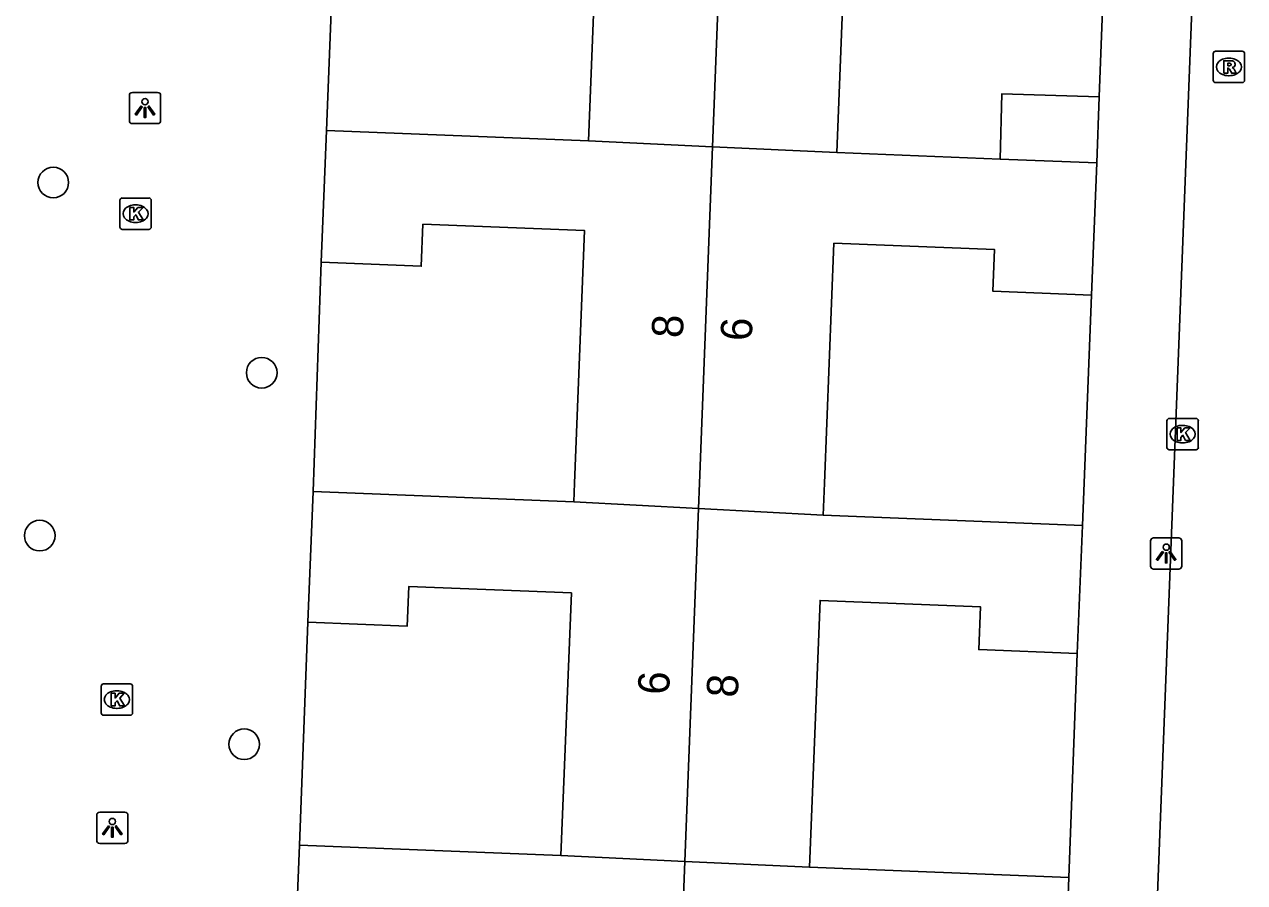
# Model space of a CAD drawing. Extents: x 160787 to 161428, y 386828 to 387483.
# Drawn here: x 161235.24 to 161274.2, y 387237.25 to 387264.64 of the extents above; entities that cross this region are included whole.
import ezdxf

# ---------------------------------------------------------------- set-up
doc = ezdxf.new("R2010")
doc.units = 0
for name, color, linetype in [('IMGEO_Boom', 7, 'Continuous'), ('IMGEO_Kolk', 7, 'Continuous'), ('IMGEO_Lichtpunt', 7, 'Continuous'), ('IMGEO_Muur', 7, 'Continuous'), ('IMGEO_Pand', 7, 'Continuous'), ('IMGEO_Pand_nummerreeks', 7, 'Continuous'), ('IMGEO_Rioolput', 7, 'Continuous'), ('IMGEO_Voetpad_open', 7, 'Continuous')]:
    doc.layers.add(name, color=color, linetype=linetype)

msp = doc.modelspace()

# ---------------------------------------------------------------- linework, layer by layer
at = {"layer": 'IMGEO_Boom'}
for centre in [(161236.166, 387259.594), (161242.821, 387253.522), (161235.734, 387248.322), (161242.262, 387241.662)]:
    msp.add_circle(centre, 0.489, dxfattribs=at)
at = {"layer": 'IMGEO_Kolk'}
for p, q in [((161238.294, 387258.174), (161238.294, 387259.026)), ((161238.369, 387259.1), (161239.221, 387259.1)), ((161238.782, 387258.88), (161238.807, 387258.88)), ((161239.295, 387259.026), (161239.295, 387258.174)), ((161239.221, 387258.1), (161238.369, 387258.1)), ((161238.805, 387258.32), (161238.78, 387258.32)), ((161271.725, 387251.137), (161271.725, 387251.989)), ((161271.8, 387252.063), (161272.652, 387252.063)), ((161272.213, 387251.843), (161272.238, 387251.843)), ((161272.726, 387251.989), (161272.726, 387251.137)), ((161272.652, 387251.063), (161271.8, 387251.063)), ((161272.236, 387251.283), (161272.211, 387251.283)), ((161237.696, 387242.663), (161237.696, 387243.515)), ((161237.771, 387243.589), (161238.623, 387243.589)), ((161238.184, 387243.369), (161238.209, 387243.369)), ((161238.697, 387243.515), (161238.697, 387242.663)), ((161238.623, 387242.589), (161237.771, 387242.589)), ((161238.207, 387242.809), (161238.182, 387242.809))]:
    msp.add_line(p, q, dxfattribs=at)
for points in [[(161238.294, 387258.174), (161238.294, 387259.026)], [(161238.369, 387259.1), (161239.221, 387259.1)], [(161238.615, 387258.8), (161238.738, 387258.8), (161238.738, 387258.649), (161238.868, 387258.8), (161239.032, 387258.8), (161238.886, 387258.649), (161239.039, 387258.4), (161238.887, 387258.4), (161238.802, 387258.564), (161238.738, 387258.497), (161238.738, 387258.4), (161238.615, 387258.4), (161238.615, 387258.8)], [(161239.295, 387259.026), (161239.295, 387258.174)], [(161239.221, 387258.1), (161238.369, 387258.1)], [(161271.725, 387251.137), (161271.725, 387251.989)], [(161271.8, 387252.063), (161272.652, 387252.063)], [(161272.726, 387251.989), (161272.726, 387251.137)], [(161272.046, 387251.763), (161272.169, 387251.763), (161272.169, 387251.612), (161272.299, 387251.763), (161272.463, 387251.763), (161272.317, 387251.612), (161272.47, 387251.363), (161272.318, 387251.363), (161272.233, 387251.527), (161272.169, 387251.46), (161272.169, 387251.363), (161272.046, 387251.363), (161272.046, 387251.763)], [(161272.652, 387251.063), (161271.8, 387251.063)], [(161237.696, 387242.663), (161237.696, 387243.515)], [(161237.771, 387243.589), (161238.623, 387243.589)], [(161238.017, 387243.289), (161238.14, 387243.289), (161238.14, 387243.138), (161238.27, 387243.289), (161238.434, 387243.289), (161238.288, 387243.138), (161238.441, 387242.889), (161238.289, 387242.889), (161238.204, 387243.053), (161238.14, 387242.986), (161238.14, 387242.889), (161238.017, 387242.889), (161238.017, 387243.289)], [(161238.697, 387243.515), (161238.697, 387242.663)], [(161238.623, 387242.589), (161237.771, 387242.589)]]:
    msp.add_lwpolyline(points, dxfattribs=at)
for centre, start, end in [((161238.371, 387259.024), 91.552, 178.448), ((161238.371, 387259.024), 91.552, 178.448), ((161239.219, 387259.024), 1.552, 88.448), ((161239.219, 387259.024), 1.552, 88.448), ((161238.371, 387258.176), 181.552, 268.448), ((161238.371, 387258.176), 181.552, 268.448), ((161239.219, 387258.176), 271.552, 358.448), ((161239.219, 387258.176), 271.552, 358.448), ((161271.802, 387251.987), 91.552, 178.448), ((161271.802, 387251.987), 91.552, 178.448), ((161272.65, 387251.987), 1.552, 88.448), ((161272.65, 387251.987), 1.552, 88.448), ((161271.802, 387251.139), 181.552, 268.448), ((161271.802, 387251.139), 181.552, 268.448), ((161272.65, 387251.139), 271.552, 358.448), ((161272.65, 387251.139), 271.552, 358.448), ((161237.773, 387243.513), 91.552, 178.448), ((161237.773, 387243.513), 91.552, 178.448), ((161238.621, 387243.513), 1.552, 88.448), ((161238.621, 387243.513), 1.552, 88.448), ((161237.773, 387242.665), 181.552, 268.448), ((161237.773, 387242.665), 181.552, 268.448), ((161238.621, 387242.665), 271.552, 358.448), ((161238.621, 387242.665), 271.552, 358.448)]:
    msp.add_arc(centre, 0.0765, start, end, dxfattribs=at)
for centre, major_axis, ratio, start_param, end_param in [((161238.781, 387258.6), (-0.387, 0.002), 0.722429, 4.712389, 7.853982), ((161238.806, 387258.6), (-0.39, 0.002), 0.717154, 1.570796, 4.712389), ((161272.212, 387251.563), (-0.387, 0.002), 0.722429, 4.712389, 7.853982), ((161272.237, 387251.563), (-0.39, 0.002), 0.717154, 1.570796, 4.712389), ((161238.183, 387243.089), (-0.387, 0.002), 0.722429, 4.712389, 7.853982), ((161238.208, 387243.089), (-0.39, 0.002), 0.717154, 1.570796, 4.712389)]:
    msp.add_ellipse(centre, major_axis=major_axis, ratio=ratio, start_param=start_param, end_param=end_param, dxfattribs=at)
at = {"layer": 'IMGEO_Lichtpunt'}
for p, q in [((161238.597, 387262.375), (161238.597, 387261.568)), ((161238.597, 387262.375), (161238.597, 387261.568)), ((161239.499, 387262.47), (161238.691, 387262.47)), ((161239.499, 387262.47), (161238.691, 387262.47)), ((161239.593, 387261.568), (161239.593, 387262.375)), ((161239.593, 387261.568), (161239.593, 387262.375)), ((161238.691, 387261.474), (161239.499, 387261.474)), ((161238.691, 387261.474), (161239.499, 387261.474)), ((161271.202, 387248.156), (161271.202, 387247.349)), ((161271.202, 387248.156), (161271.202, 387247.349)), ((161272.104, 387248.251), (161271.296, 387248.251)), ((161272.104, 387248.251), (161271.296, 387248.251)), ((161272.198, 387247.349), (161272.198, 387248.156)), ((161272.198, 387247.349), (161272.198, 387248.156)), ((161271.296, 387247.255), (161272.104, 387247.255)), ((161271.296, 387247.255), (161272.104, 387247.255)), ((161237.554, 387239.4), (161237.554, 387238.593)), ((161237.554, 387239.4), (161237.554, 387238.593)), ((161238.456, 387239.495), (161237.648, 387239.495)), ((161238.456, 387239.495), (161237.648, 387239.495)), ((161238.55, 387238.593), (161238.55, 387239.4)), ((161238.55, 387238.593), (161238.55, 387239.4)), ((161237.648, 387238.499), (161238.456, 387238.499)), ((161237.648, 387238.499), (161238.456, 387238.499))]:
    msp.add_line(p, q, dxfattribs=at)
for points in [[(161238.971, 387262.039), (161239.01, 387262.011), (161238.822, 387261.749), (161238.784, 387261.776), (161238.971, 387262.039)], [(161239.073, 387261.991), (161239.12, 387261.991), (161239.12, 387261.669), (161239.073, 387261.669), (161239.073, 387261.991)], [(161239.183, 387262.011), (161239.221, 387262.038), (161239.408, 387261.776), (161239.369, 387261.748), (161239.183, 387262.011)], [(161271.576, 387247.82), (161271.615, 387247.792), (161271.427, 387247.53), (161271.389, 387247.557), (161271.576, 387247.82)], [(161271.678, 387247.772), (161271.725, 387247.772), (161271.725, 387247.45), (161271.678, 387247.45), (161271.678, 387247.772)], [(161271.788, 387247.792), (161271.826, 387247.819), (161272.013, 387247.557), (161271.974, 387247.529), (161271.788, 387247.792)], [(161237.928, 387239.064), (161237.967, 387239.036), (161237.779, 387238.774), (161237.741, 387238.801), (161237.928, 387239.064)], [(161238.03, 387239.016), (161238.077, 387239.016), (161238.077, 387238.694), (161238.03, 387238.694), (161238.03, 387239.016)], [(161238.14, 387239.036), (161238.178, 387239.063), (161238.365, 387238.801), (161238.326, 387238.773), (161238.14, 387239.036)]]:
    msp.add_lwpolyline(points, dxfattribs=at)
for centre in [(161239.096, 387262.173), (161271.701, 387247.954), (161238.053, 387239.198)]:
    msp.add_circle(centre, 0.0994, dxfattribs=at)
for centre, start, end in [((161238.691, 387262.375), 90, 180), ((161238.691, 387262.375), 90, 180), ((161239.499, 387262.375), 0, 90), ((161239.499, 387262.375), 0, 90), ((161238.691, 387261.568), 180, 270), ((161238.691, 387261.568), 180, 270), ((161239.499, 387261.568), 270, 0), ((161239.499, 387261.568), 270, 360), ((161271.296, 387248.156), 90, 180), ((161271.296, 387248.156), 90, 180), ((161272.104, 387248.156), 0, 90), ((161272.104, 387248.156), 0, 90), ((161271.296, 387247.349), 180, 270), ((161271.296, 387247.349), 180, 270), ((161272.104, 387247.349), 270, 0), ((161272.104, 387247.349), 270, 360), ((161237.648, 387239.4), 90, 180), ((161237.648, 387239.4), 90, 180), ((161238.456, 387239.4), 0, 90), ((161238.456, 387239.4), 0, 90), ((161237.648, 387238.593), 180, 270), ((161237.648, 387238.593), 180, 270), ((161238.456, 387238.593), 270, 0), ((161238.456, 387238.593), 270, 360)]:
    msp.add_arc(centre, 0.0946, start, end, dxfattribs=at)
at = {"layer": 'IMGEO_Muur'}
for points in [[(161245.172, 387268.319), (161244.893, 387261.255)], [(161269.755, 387267.338), (161269.563, 387262.328)], [(161244.725, 387257.051), (161244.463, 387249.735)], [(161269.314, 387255.996), (161269.024, 387248.648)], [(161244.297, 387245.564), (161244.025, 387238.443)], [(161268.861, 387244.561), (161268.595, 387237.411)]]:
    msp.add_lwpolyline(points, dxfattribs=at)
at = {"layer": 'IMGEO_Pand'}
for points in [[(161257.652, 387271.983), (161257.217, 387260.735)], [(161245.172, 387268.319), (161248.341, 387268.193), (161248.393, 387269.487), (161253.588, 387269.281), (161253.255, 387260.922)], [(161261.179, 387260.549), (161261.513, 387268.942), (161266.616, 387268.739), (161266.566, 387267.465), (161269.755, 387267.338)], [(161269.563, 387262.328), (161266.454, 387262.429), (161266.401, 387260.341)], [(161269.563, 387262.328), (161269.482, 387260.218)], [(161244.725, 387257.051), (161244.893, 387261.255)], [(161253.255, 387260.922), (161244.893, 387261.255)], [(161257.217, 387260.735), (161253.255, 387260.922)], [(161257.217, 387260.735), (161256.802, 387250), (161256.771, 387249.19)], [(161261.179, 387260.549), (161257.217, 387260.735)], [(161266.401, 387260.341), (161261.179, 387260.549)], [(161269.482, 387260.218), (161266.401, 387260.341)], [(161269.482, 387260.218), (161269.314, 387255.996)], [(161244.725, 387257.051), (161247.917, 387256.924), (161247.97, 387258.264), (161253.129, 387258.059), (161252.809, 387250), (161252.785, 387249.405)], [(161260.747, 387248.977), (161260.788, 387250), (161261.093, 387257.656), (161266.222, 387257.452), (161266.169, 387256.121), (161269.314, 387255.996)], [(161244.297, 387245.564), (161244.463, 387249.735)], [(161252.785, 387249.405), (161244.463, 387249.735)], [(161252.785, 387249.405), (161256.771, 387249.19)], [(161256.771, 387249.19), (161256.335, 387237.925)], [(161256.771, 387249.19), (161260.747, 387248.977)], [(161269.024, 387248.648), (161260.747, 387248.977)], [(161269.024, 387248.648), (161268.861, 387244.561)], [(161244.297, 387245.564), (161247.469, 387245.437), (161247.519, 387246.7), (161252.71, 387246.494), (161252.377, 387238.111)], [(161260.31, 387237.741), (161260.649, 387246.255), (161265.767, 387246.051), (161265.713, 387244.686), (161268.861, 387244.561)], [(161243.858, 387234.254), (161244.025, 387238.443)], [(161252.377, 387238.111), (161244.025, 387238.443)], [(161256.335, 387237.925), (161252.377, 387238.111)], [(161255.899, 387226.628), (161256.335, 387237.925)], [(161256.335, 387237.925), (161260.31, 387237.741)], [(161268.595, 387237.411), (161260.31, 387237.741)], [(161268.595, 387237.411), (161268.428, 387233.219)]]:
    msp.add_lwpolyline(points, dxfattribs=at)
at = {"layer": 'IMGEO_Rioolput'}
for p, q in [((161273.202, 387262.858), (161273.202, 387263.71)), ((161273.277, 387263.784), (161274.129, 387263.784)), ((161273.69, 387263.564), (161273.715, 387263.564)), ((161274.203, 387263.71), (161274.203, 387262.858)), ((161274.129, 387262.784), (161273.277, 387262.784)), ((161273.713, 387263.004), (161273.688, 387263.004))]:
    msp.add_line(p, q, dxfattribs=at)
for points in [[(161273.202, 387262.858), (161273.202, 387263.71)], [(161273.277, 387263.784), (161274.129, 387263.784)], [(161273.791, 387263.482), (161273.539, 387263.484), (161273.539, 387263.084)], [(161274.203, 387263.71), (161274.203, 387262.858)], [(161273.539, 387263.084), (161273.663, 387263.084), (161273.663, 387263.246), (161273.674, 387263.246)], [(161273.717, 387263.403), (161273.663, 387263.403), (161273.663, 387263.322)], [(161273.663, 387263.322), (161273.715, 387263.322)], [(161273.721, 387263.217), (161273.792, 387263.084), (161273.932, 387263.084), (161273.867, 387263.21)], [(161274.129, 387262.784), (161273.277, 387262.784)]]:
    msp.add_lwpolyline(points, dxfattribs=at)
for centre, radius, start, end in [((161273.279, 387263.708), 0.0765, 91.552, 178.448), ((161273.279, 387263.708), 0.0765, 91.552, 178.448), ((161273.79, 387263.372), 0.109, 350.3612, 89.416), ((161274.127, 387263.708), 0.0765, 1.552, 88.448), ((161274.127, 387263.708), 0.0765, 1.552, 88.448), ((161273.673, 387263.193), 0.0533, 26.0293, 88.6989), ((161273.699, 387263.511), 0.19, 274.7715, 282.9687), ((161273.723, 387263.307), 0.0964, 77.0061, 93.1865), ((161273.737, 387263.364), 0.0378, 276.6634, 79.6772), ((161273.788, 387263.372), 0.112, 277.5842, 350.9817), ((161273.772, 387263.157), 0.108, 29.5134, 73.7905), ((161273.279, 387262.86), 0.0765, 181.552, 268.448), ((161273.279, 387262.86), 0.0765, 181.552, 268.448), ((161274.127, 387262.86), 0.0765, 271.552, 358.448), ((161274.127, 387262.86), 0.0765, 271.552, 358.448)]:
    msp.add_arc(centre, radius, start, end, dxfattribs=at)
for centre, major_axis, ratio, start_param, end_param in [((161273.689, 387263.284), (-0.387, 0.002), 0.722429, 4.712389, 7.853982), ((161273.714, 387263.284), (-0.39, 0.002), 0.717154, 1.570796, 4.712389)]:
    msp.add_ellipse(centre, major_axis=major_axis, ratio=ratio, start_param=start_param, end_param=end_param, dxfattribs=at)
at = {"layer": 'IMGEO_Voetpad_open'}
for points in [[(161270.807, 387220.973), (161272.761, 387271.438)], [(161244.893, 387261.255), (161245.172, 387268.319)], [(161269.755, 387267.338), (161269.563, 387262.328)], [(161244.463, 387249.735), (161244.725, 387257.051)], [(161269.314, 387255.996), (161269.024, 387248.648)], [(161244.025, 387238.443), (161244.297, 387245.564)], [(161268.861, 387244.561), (161268.595, 387237.411)]]:
    msp.add_lwpolyline(points, dxfattribs=at)

# ---------------------------------------------------------------- texts
at = {"layer": 'IMGEO_Pand_nummerreeks'}
for s, rotation, p in [('8', 87.7903, (161256.267, 387254.618)), ('6', 87.7593, (161258.467, 387254.522)), ('6', 87.7903, (161255.828, 387243.23)), ('8', 87.7593, (161258.022, 387243.142))]:
    msp.add_text(s, height=1, rotation=rotation, dxfattribs=at).set_placement(p)

doc.saveas('drawing.dxf')
